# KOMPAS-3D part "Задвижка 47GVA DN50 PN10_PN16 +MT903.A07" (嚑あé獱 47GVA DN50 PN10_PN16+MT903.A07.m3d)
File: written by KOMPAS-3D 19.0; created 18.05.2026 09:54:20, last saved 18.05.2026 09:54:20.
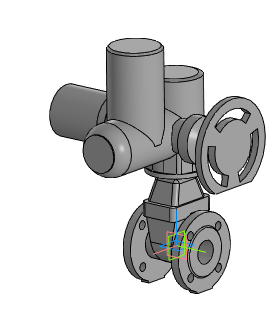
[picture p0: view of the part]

Document properties: Автор: Энергия; Полное имя файла: ..\Задвижка 47GVA DN50_DN1000MT903.A\Задвижка 47GVA DN50 PN10_PN16+MT903.A07.a3d

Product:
- Part/product: Задвижка 47GVA DN50 PN10_PN16 +MT903.A07
    Масса: 81.2736
  - Body: Электропривод МТ903.А07 без блока управления
      Масса: 65.4738
  - Body: Задвижка 47GVA DN50 PN10_PN16 без исполн. мех.
      Масса: 15.7998

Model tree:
1. Операция без истории:1
2. Операция без истории:2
